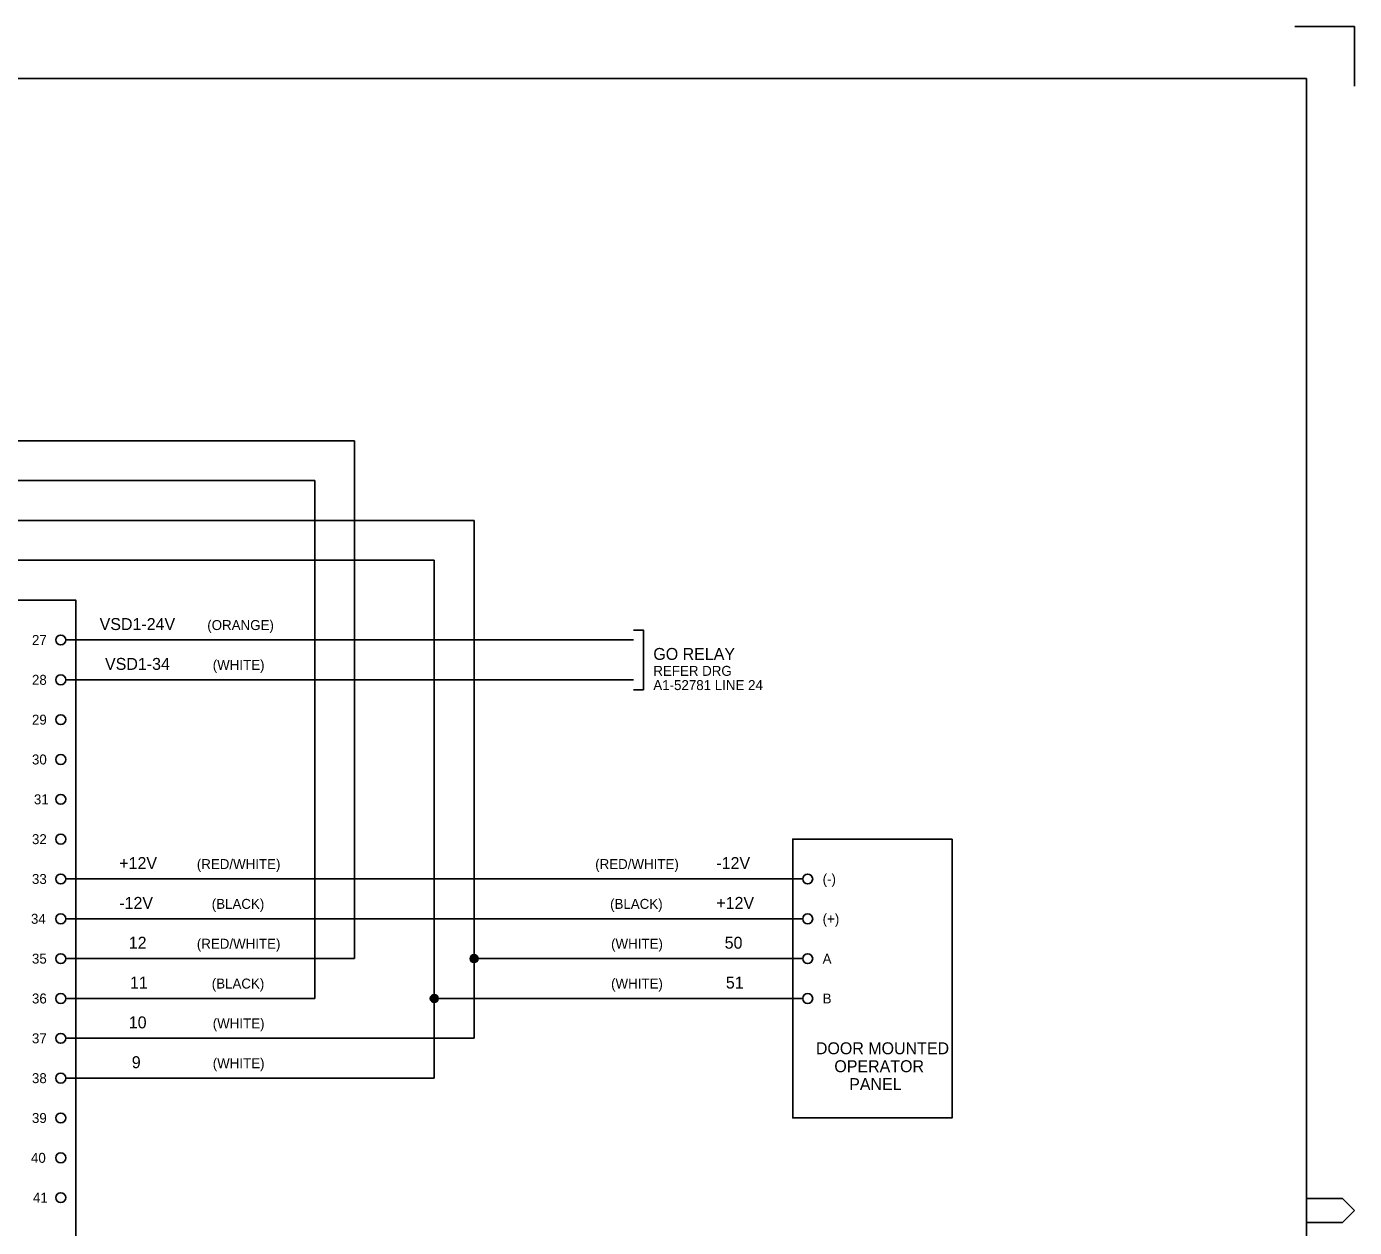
# Model space of a CAD drawing. Extents: x 0 to 841, y 0 to 594.
# Drawn here: x 507.7 to 841, y 292.5 to 594 of the extents above; entities that cross this region are included whole.
import ezdxf

# ---------------------------------------------------------------- set-up
doc = ezdxf.new("R2010")
doc.units = 0
for name, color, linetype in [('A1BORDER', 7, 'Continuous'), ('Level 1', 7, 'Continuous'), ('Level 10', 7, 'Continuous'), ('Level 5', 7, 'Continuous')]:
    doc.layers.add(name, color=color, linetype=linetype)

msp = doc.modelspace()

# ---------------------------------------------------------------- linework, layer by layer
at = {"layer": 'A1BORDER'}
for p, q in [((826, 594), (841, 594)), ((841, 579), (841, 594)), ((28, 581), (829, 581)), ((829, 581), (829, 15)), ((829, 299.76), (838, 299.76)), ((838, 299.76), (841, 296.76)), ((838, 293.76), (841, 296.76)), ((829, 293.76), (838, 293.76))]:
    msp.add_line(p, q, dxfattribs=at)
at = {"layer": 'Level 1'}
for p, q in [((227.5, 490), (590, 490)), ((590, 360), (590, 490)), ((227.5, 480), (580, 480)), ((580, 350), (580, 480)), ((227.5, 470), (620, 470)), ((620, 340), (620, 470)), ((227.5, 460), (610, 460)), ((610, 330), (610, 460)), ((517.5, 440), (660, 440)), ((517.5, 430), (660, 430)), ((517.5, 380), (702.5, 380)), ((517.5, 370), (702.5, 370)), ((517.5, 360), (590, 360)), ((620, 360), (702.5, 360)), ((517.5, 350), (580, 350)), ((610, 350), (702.5, 350)), ((517.5, 340), (620, 340)), ((517.5, 330), (610, 330))]:
    msp.add_line(p, q, dxfattribs=at)
for points in [[(320, 450), (520, 450), (520, 180), (320, 180)], [(740, 390), (700, 390), (700, 320), (740, 320)]]:
    msp.add_lwpolyline(points, close=True, dxfattribs=at)
msp.add_lwpolyline([(660, 442.5), (662.5, 442.5), (662.5, 427.5), (660, 427.5)], dxfattribs=at)
at = {"layer": 'Level 10'}
for p, q in [((619.05, 360.3), (620.95, 360.3)), ((619.2, 360.6), (620.8, 360.6)), ((619.56, 360.9), (620.44, 360.9)), ((620, 361), (620, 361)), ((619, 360), (620.99, 360)), ((619.05, 359.7), (620.95, 359.7)), ((619.2, 359.4), (620.8, 359.4)), ((619.56, 359.1), (620.44, 359.1)), ((609.05, 350.3), (610.95, 350.3)), ((609.2, 350.6), (610.8, 350.6)), ((609.56, 350.9), (610.44, 350.9)), ((610, 351), (610, 351)), ((609, 350), (610.99, 350)), ((609.05, 349.7), (610.95, 349.7)), ((609.2, 349.4), (610.8, 349.4)), ((609.56, 349.1), (610.44, 349.1))]:
    msp.add_line(p, q, dxfattribs=at)
for centre in [(620, 360), (610, 350)]:
    msp.add_circle(centre, 1, dxfattribs=at)
at = {"layer": 'Level 5'}
for centre in [(516.25, 440), (516.25, 430), (516.25, 420), (516.25, 410), (516.25, 400), (516.25, 390), (516.25, 380), (703.75, 380), (516.25, 370), (703.75, 370), (516.25, 360), (703.75, 360), (516.25, 350), (703.75, 350), (516.25, 340), (516.25, 330), (516.25, 320), (516.25, 310), (516.25, 300)]:
    msp.add_circle(centre, 1.25, dxfattribs=at)

# ---------------------------------------------------------------- texts
at = {"layer": 'Level 1'}
for s, height, p in [('27', 2.5, (509.02, 438.75)), ('GO RELAY', 3, (665, 435)), ('REFER DRG', 2.5, (665, 431)), ('28', 2.5, (509.02, 428.75)), ('A1-52781 LINE 24', 2.5, (665, 427.43)), ('29', 2.5, (509.02, 418.75)), ('30', 2.5, (509.02, 408.75)), ('31', 2.5, (509.51, 398.75)), ('32', 2.5, (509.02, 388.75)), ('33', 2.5, (509.02, 378.75)), ('(-)', 2.5, (707.5, 378.75)), ('34', 2.5, (508.77, 368.75)), ('(+)', 2.5, (707.5, 368.75)), ('35', 2.5, (509.02, 358.75)), ('A', 2.5, (707.5, 358.75)), ('36', 2.5, (509.02, 348.75)), ('B', 2.5, (707.5, 348.75)), ('37', 2.5, (509.02, 338.75)), ('38', 2.5, (509.02, 328.75)), ('39', 2.5, (509.02, 318.75)), ('40', 2.5, (508.77, 308.75)), ('41', 2.5, (509.27, 298.75))]:
    msp.add_text(s, height=height, dxfattribs=at).set_placement(p)
at = {"layer": 'Level 5'}
for s, height, p in [('VSD1-24V', 3, (526.01, 442.5)), ('(ORANGE)', 2.5, (553.03, 442.5)), ('VSD1-34', 3, (527.36, 432.5)), ('(WHITE)', 2.5, (554.4, 432.5)), ('+12V', 3, (530.94, 382.5)), ('(RED/WHITE)', 2.5, (550.41, 382.5)), ('(RED/WHITE)', 2.5, (650.41, 382.5)), ('-12V', 3, (680.82, 382.5)), ('-12V', 3, (530.94, 372.5)), ('(BLACK)', 2.5, (554.15, 372.5)), ('(BLACK)', 2.5, (654.15, 372.5)), ('+12V', 3, (680.82, 372.5)), ('12', 3, (533.33, 362.5)), ('(RED/WHITE)', 2.5, (550.41, 362.5)), ('(WHITE)', 2.5, (654.4, 362.5)), ('50', 3, (682.91, 362.5)), ('11', 3, (533.63, 352.5)), ('(BLACK)', 2.5, (554.15, 352.5)), ('(WHITE)', 2.5, (654.4, 352.5)), ('51', 3, (683.21, 352.5)), ('10', 3, (533.33, 342.5)), ('(WHITE)', 2.5, (554.4, 342.5)), ('DOOR MOUNTED', 3, (705.81, 336)), ('9', 3, (534.08, 332.5)), ('(WHITE)', 2.5, (554.4, 332.5)), ('OPERATOR', 3, (710.44, 331.5)), ('PANEL', 3, (714.17, 327))]:
    msp.add_text(s, height=height, dxfattribs=at).set_placement(p)

doc.saveas('drawing.dxf')
